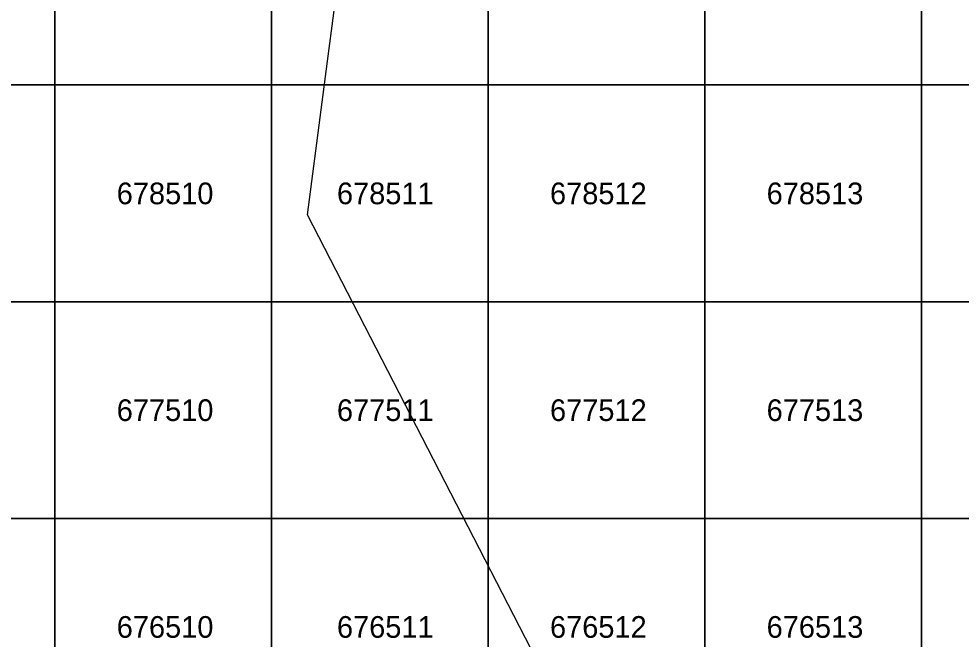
# Model space of a CAD drawing. Extents: x 25485000 to 25520000, y 6656775 to 6690000.
# Drawn here: x 25509833 to 25514183, y 6676444 to 6679305 of the extents above; entities that cross this region are included whole.
import ezdxf

# ---------------------------------------------------------------- set-up
doc = ezdxf.new("R2010")
doc.units = 0
doc.layers.add('Level 63', color=7, linetype='Continuous')

msp = doc.modelspace()

# ---------------------------------------------------------------- linework, layer by layer
at = {"layer": 'Level 63'}
for points in [[(25509000, 6679000), (25510000, 6679000), (25510000, 6680000), (25509000, 6680000)], [(25510000, 6679000), (25511000, 6679000), (25511000, 6680000), (25510000, 6680000)], [(25511000, 6679000), (25512000, 6679000), (25512000, 6680000), (25511000, 6680000)], [(25512000, 6679000), (25513000, 6679000), (25513000, 6680000), (25512000, 6680000)], [(25513000, 6679000), (25514000, 6679000), (25514000, 6680000), (25513000, 6680000)], [(25514000, 6679000), (25515000, 6679000), (25515000, 6680000), (25514000, 6680000)], [(25509000, 6678000), (25510000, 6678000), (25510000, 6679000), (25509000, 6679000)], [(25510000, 6678000), (25511000, 6678000), (25511000, 6679000), (25510000, 6679000)], [(25511000, 6678000), (25512000, 6678000), (25512000, 6679000), (25511000, 6679000)], [(25512000, 6678000), (25513000, 6678000), (25513000, 6679000), (25512000, 6679000)], [(25513000, 6678000), (25514000, 6678000), (25514000, 6679000), (25513000, 6679000)], [(25514000, 6678000), (25515000, 6678000), (25515000, 6679000), (25514000, 6679000)], [(25509000, 6677000), (25510000, 6677000), (25510000, 6678000), (25509000, 6678000)], [(25510000, 6677000), (25511000, 6677000), (25511000, 6678000), (25510000, 6678000)], [(25511000, 6677000), (25512000, 6677000), (25512000, 6678000), (25511000, 6678000)], [(25512000, 6677000), (25513000, 6677000), (25513000, 6678000), (25512000, 6678000)], [(25513000, 6677000), (25514000, 6677000), (25514000, 6678000), (25513000, 6678000)], [(25514000, 6677000), (25515000, 6677000), (25515000, 6678000), (25514000, 6678000)], [(25509000, 6676000), (25510000, 6676000), (25510000, 6677000), (25509000, 6677000)], [(25510000, 6676000), (25511000, 6676000), (25511000, 6677000), (25510000, 6677000)], [(25511000, 6676000), (25512000, 6676000), (25512000, 6677000), (25511000, 6677000)], [(25512000, 6676000), (25513000, 6676000), (25513000, 6677000), (25512000, 6677000)], [(25513000, 6676000), (25514000, 6676000), (25514000, 6677000), (25513000, 6677000)], [(25514000, 6676000), (25515000, 6676000), (25515000, 6677000), (25514000, 6677000)]]:
    msp.add_lwpolyline(points, close=True, dxfattribs=at)
msp.add_lwpolyline([(25512224.3, 6676346.7), (25511165.3, 6678400.9), (25511257.6, 6679109.3), (25511288, 6679331.7), (25511304.1, 6679474.4), (25511325.7, 6679703.9), (25511334.4, 6679796.6), (25511009.8, 6679625), (25510891.7, 6679562.6), (25510842.1, 6679533.1), (25510696.9, 6679450.1), (25510539.5, 6679371.7), (25510121, 6679588.2), (25510096.8, 6679562.8), (25509256.4, 6679905)], dxfattribs=at)

# ---------------------------------------------------------------- texts
for s, p in [('678510', (25510285.1, 6678450)), ('678511', (25511301.6, 6678450)), ('678512', (25512285.1, 6678450)), ('678513', (25513285.1, 6678450)), ('677510', (25510285.1, 6677450)), ('677511', (25511301.6, 6677450)), ('677512', (25512285.1, 6677450)), ('677513', (25513285.1, 6677450)), ('676510', (25510285.1, 6676450)), ('676511', (25511301.6, 6676450)), ('676512', (25512285.1, 6676450)), ('676513', (25513285.1, 6676450))]:
    msp.add_text(s, height=100, dxfattribs=at).set_placement(p)

doc.saveas('drawing.dxf')
